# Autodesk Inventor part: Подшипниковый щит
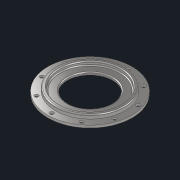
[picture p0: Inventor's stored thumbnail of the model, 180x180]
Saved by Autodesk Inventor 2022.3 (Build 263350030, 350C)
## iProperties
Created: 2022-08
Part Number: Подшипниковый щит
Material: Сталь 40ХНМА
Document SubType Name: Modeling
Designer: Карташов
Density: 7.85 g/cm^3
Appearance: С умеренной полировкой
Author: Карташов
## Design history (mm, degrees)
sketch "Эскиз1"
  geometry: L1 (0, 0)-(0, 34.001); L2 (47, -6)-(85, -6); L3 (85, -6)-(85, -1); L4 (85, -1)-(70, -1); L5 (70, -1)-(70, 5); L6 (68, 7)-(64, 7); L7 (62, 5)-(62, 2); L8 (45, -4)-(45, -2); L9 (47, 0)-(60, 0); A1 r 2 centre (60, 2) between (60, 0) and (62, 2); A2 r 2 centre (68, 5) between (70, 5) and (68, 7); A3 r 2 centre (64, 5) between (64, 7) and (62, 5); A4 r 2 centre (47, -2) between (47, 0) and (45, -2); A5 r 2 centre (47, -4) between (45, -4) and (47, -6); 6 further points
  constraints: 18 end point, 10 point on circle, 10 tangent, 8 point on line, 5 centre point, 4 horizontal, 4 vertical, 2 midpoint, 1 equal radius, 1 horizontal alignment, 1 perpendicular
  dimensions: "d0" = 140 diameter of L5 point (0, 17); "d1" = 170 diameter of L3 L1; "d4" = 5 distance of L2.end L3.end; "d6" = 8 distance of point (70, 7) point (62, 7); "d7" = 2 radius of A1; "d24" = 2 radius of A2; "d25" = 2 radius of A3 (derived); "d27" = 90 diameter of L8 L1; "d28" = 13 distance between parallel lines of L6 L2; "d29" = 7 distance between parallel lines of L6 L9; "d30" = 2 radius of A4
revolve "Вращение1" sketch "Эскиз1" stored, may be unused: angle "d9" = 90 deg
sketch "Эскиз2"
  geometry: C1 r 70 at (0, 0) reference; C2 r 85 at (0, 0) reference; 2 further points
  constraints: 1 vertical alignment
  dimensions: "d10" = 77.5 distance of point (0, 0) point (0, -77.5)
  node "Спроецированная петля1"
sketch "Эскиз3"
  geometry: 2 further points
hole "Отверстие1" sketch "Эскиз3" at (0, 77.5) diameter "d11" = 8; stored, may be unused: countersink angle "d15" = 90 deg, drill point angle "d17" = 0 deg; dims "d12" = 6, "d13" = 13, "d14" = 1, "d16" = 22.5
pattern_circular "Круговой массив1" dims angle "d19" = 360 deg
node "Твердое тело1"
